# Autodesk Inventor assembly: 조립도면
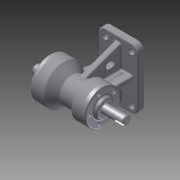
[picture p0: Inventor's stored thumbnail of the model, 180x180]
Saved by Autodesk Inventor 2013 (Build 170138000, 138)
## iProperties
Created: 2015-08
Part Number: 조립도면
Document SubType Name: Weldment
Designer: dfdfd
Weld Material: Welded Aluminum-6061
Author: dfdfd
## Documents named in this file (10)
- C:\Users\dfdfd\Desktop\450805V1028\조립도면.iam
- C:\Users\dfdfd\Desktop\450805V1028\M4x0.5.ipt
- C:\Users\dfdfd\Desktop\450805V1028\뒤커버.ipt
- C:\Users\dfdfd\Desktop\450805V1028\베어링 6203.ipt
- C:\Users\dfdfd\Desktop\450805V1028\베어링 6205.ipt
- C:\Users\dfdfd\Desktop\450805V1028\본체.ipt
- C:\Users\dfdfd\Desktop\450805V1028\앞커버.ipt
- C:\Users\dfdfd\Desktop\450805V1028\오일실 .ipt
- 오일실 .ipt
- C:\Users\dfdfd\Desktop\450805V1028\축.ipt
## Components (10 placed, 1 different names)
1. M4x0.5:1
2. M4x0.5:2
3. M4x0.5:3
4. M4x0.5:4
5. M4x0.5:5
6. M4x0.5:6
7. M4x0.5:7
8. M4x0.5:8
9. M4x0.5:9
10. M4x0.5:10
